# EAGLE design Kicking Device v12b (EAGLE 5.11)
OC_FARNELL: 1685056

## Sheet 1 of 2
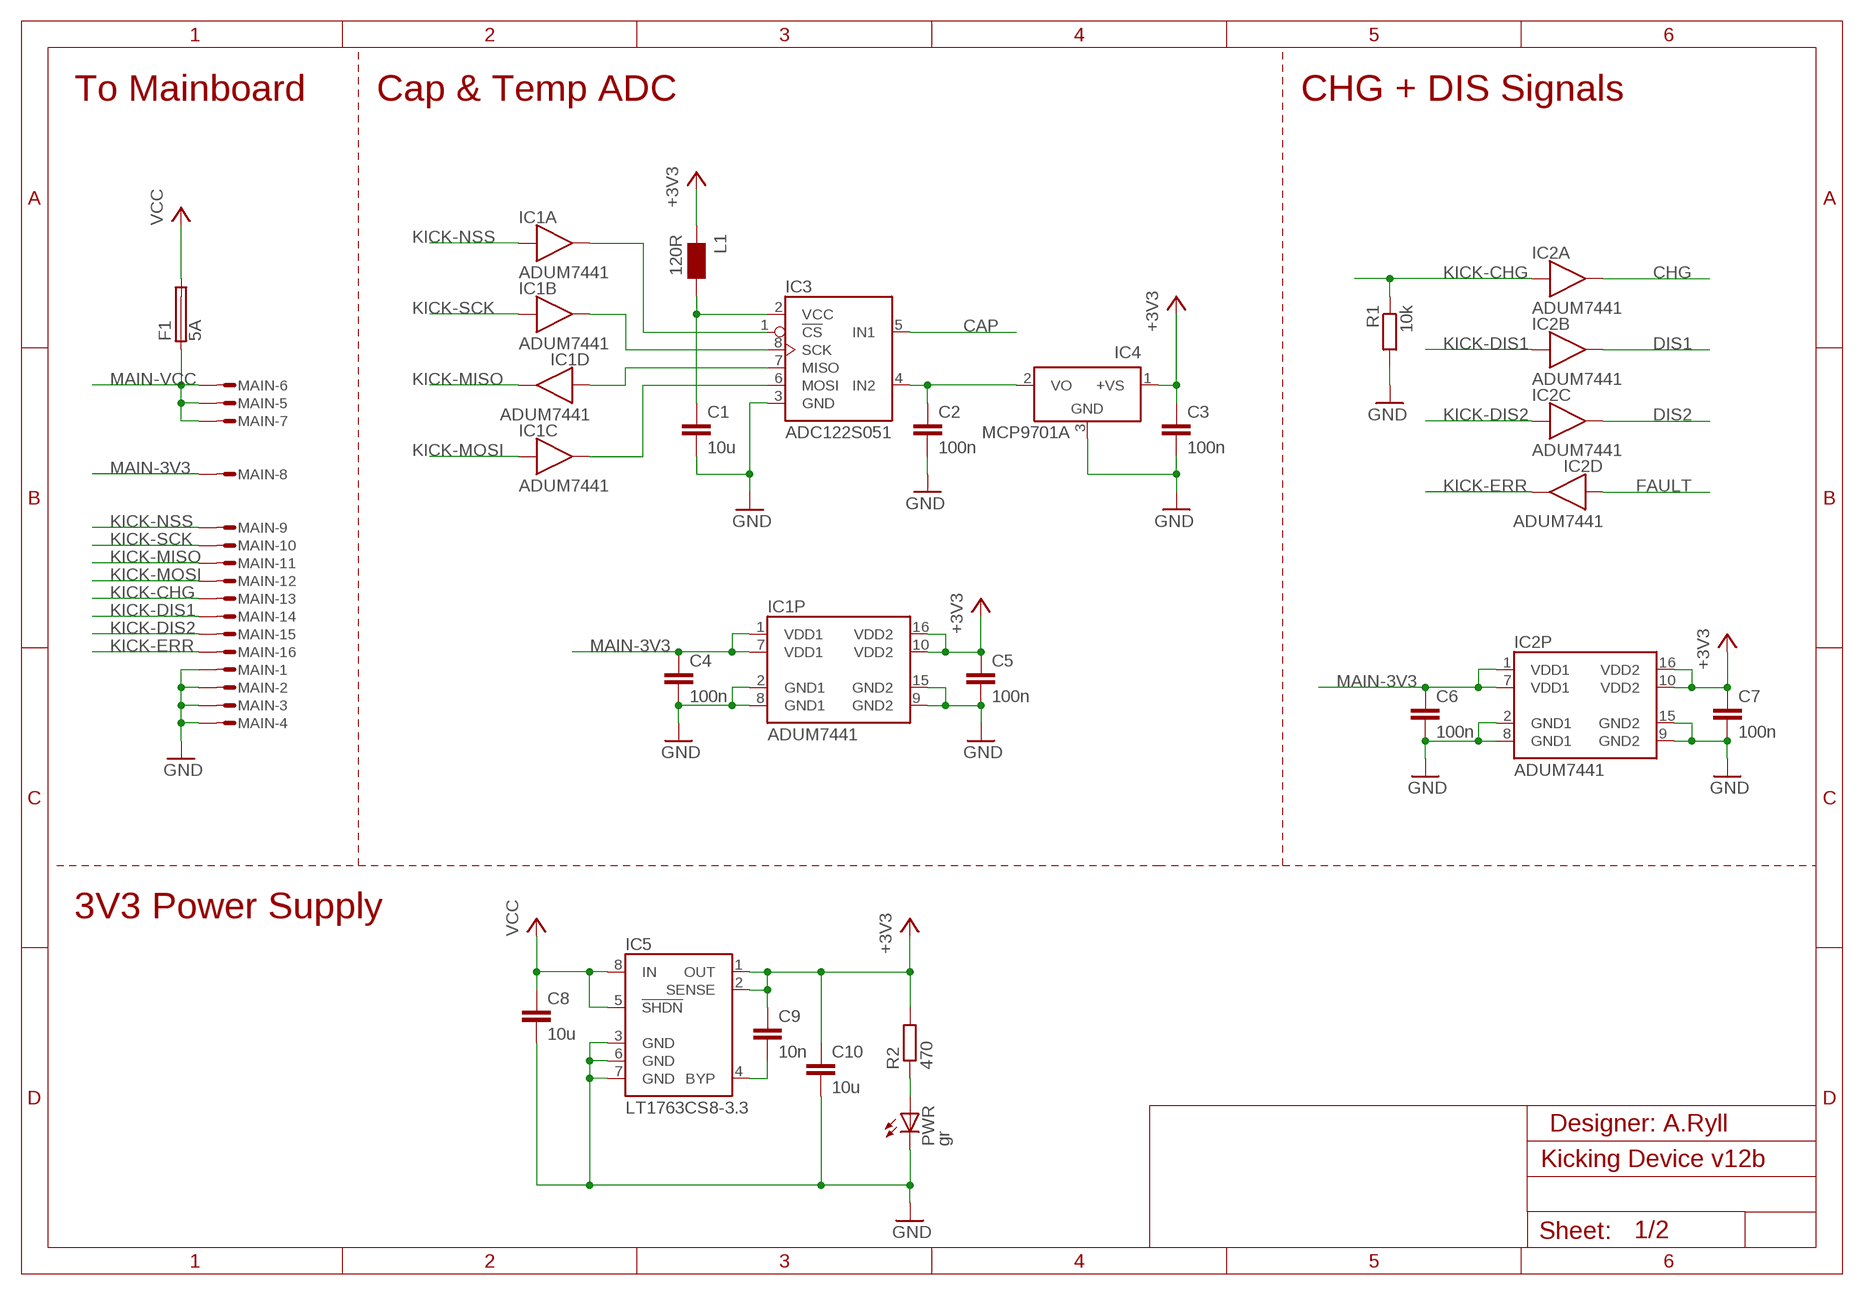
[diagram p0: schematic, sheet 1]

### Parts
C1  10u  C-EUC0603  [C0603]
C2  100n  C-EUC0603  [C0603]
C3  100n  C-EUC0603  [C0603]
C4  100n  C-EUC0603  [C0603]
C5  100n  C-EUC0603  [C0603]
C6  100n  C-EUC0603  [C0603]
C7  100n  C-EUC0603  [C0603]
C8  10u  C-EUC0805  [C0805]
C9  10n  C-EUC0603  [C0603]
C10  10u  C-EUC0603  [C0603]
F1  5A  FUSES  [1206]
IC1  ADUM7441  [QSOP16]
IC2  ADUM7441  [QSOP16]
IC3  ADC122S051  ADC__2S__1  [MSOP8]
IC4  MCP9701A  LM60S  [SOT23]
IC5  LT1763CS8-3.3  LT1763S8  [SOIC8]
L1  120R  WE-CBF_0603  [0603]
MAIN  MICROMATCH-16SMF  [MMT-F-SMD-16]
PWR  gr  LEDCHIP-LED0603  [CHIP-LED0603]
R1  10k  R-EU_R0603  [R0603]
R2  470  R-EU_R0603  [R0603]

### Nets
+3V3: C3.1 C5.1 C7.1 C9.1 C10.1 IC1.10(P:VDD2) IC1.16(P:VDD2) IC2.10(P:VDD2) IC2.16(P:VDD2) IC4.1(+VS) IC5.1(OUT) IC5.2(SENSE) L1.1 R2.2 ; also sheet 2
ADC-VCC: C1.1 IC3.2(VCC) L1.2
CAP: IC3.5(IN1) ; also sheet 2
CHG: IC2.14(A:OUT) ; also sheet 2
DIS1: IC2.13(B:OUT) ; also sheet 2
DIS2: IC2.12(C:OUT) ; also sheet 2
FAULT: IC2.11(D:IN) ; also sheet 2
GND: C1.2 C2.2 C3.2 C4.2 C5.2 C6.2 C7.2 C8.2 C10.2 IC1.2(P:GND1) IC1.8(P:GND1) IC1.9(P:GND2) IC1.15(P:GND2) IC2.2(P:GND1) IC2.8(P:GND1) IC2.9(P:GND2) IC2.15(P:GND2) IC3.3(GND) IC4.3(GND) IC5.3(GND) IC5.6(GND) IC5.7(GND) MAIN.1 MAIN.2 MAIN.3 MAIN.4 PWR.C R1.2 ; also sheet 2
KICK-CHG: IC2.3(A:IN) MAIN.13 R1.1
KICK-DIS1: IC2.4(B:IN) MAIN.14
KICK-DIS2: IC2.5(C:IN) MAIN.15
KICK-ERR: IC2.6(D:OUT) MAIN.16
KICK-MISO: IC1.6(D:OUT) MAIN.11
KICK-MOSI: IC1.5(C:IN) MAIN.12
KICK-NSS: IC1.3(A:IN) MAIN.9
KICK-SCK: IC1.4(B:IN) MAIN.10
MAIN-3V3: C4.1 C6.1 IC1.1(P:VDD1) IC1.7(P:VDD1) IC2.1(P:VDD1) IC2.7(P:VDD1) MAIN.8
MAIN-VCC: F1.1 MAIN.5 MAIN.6 MAIN.7
N$1: IC1.13(B:OUT) IC3.8(SCK)
N$3: C9.2 IC5.4(BYP)
N$7: IC1.11(D:IN) IC3.7(MISO)
N$9: PWR.A R2.1
N$15: IC1.12(C:OUT) IC3.6(MOSI)
N$16: IC1.14(A:OUT) IC3.1(!CS)
N$18: C2.1 IC3.4(IN2) IC4.2(VO)
VCC: C8.1 F1.2 IC5.5(!SHDN) IC5.8(IN) ; also sheet 2

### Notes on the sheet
- To Mainboard | Cap & Temp ADC | CHG + DIS Signals
- 3V3 Power Supply
- Designer: A.Ryll

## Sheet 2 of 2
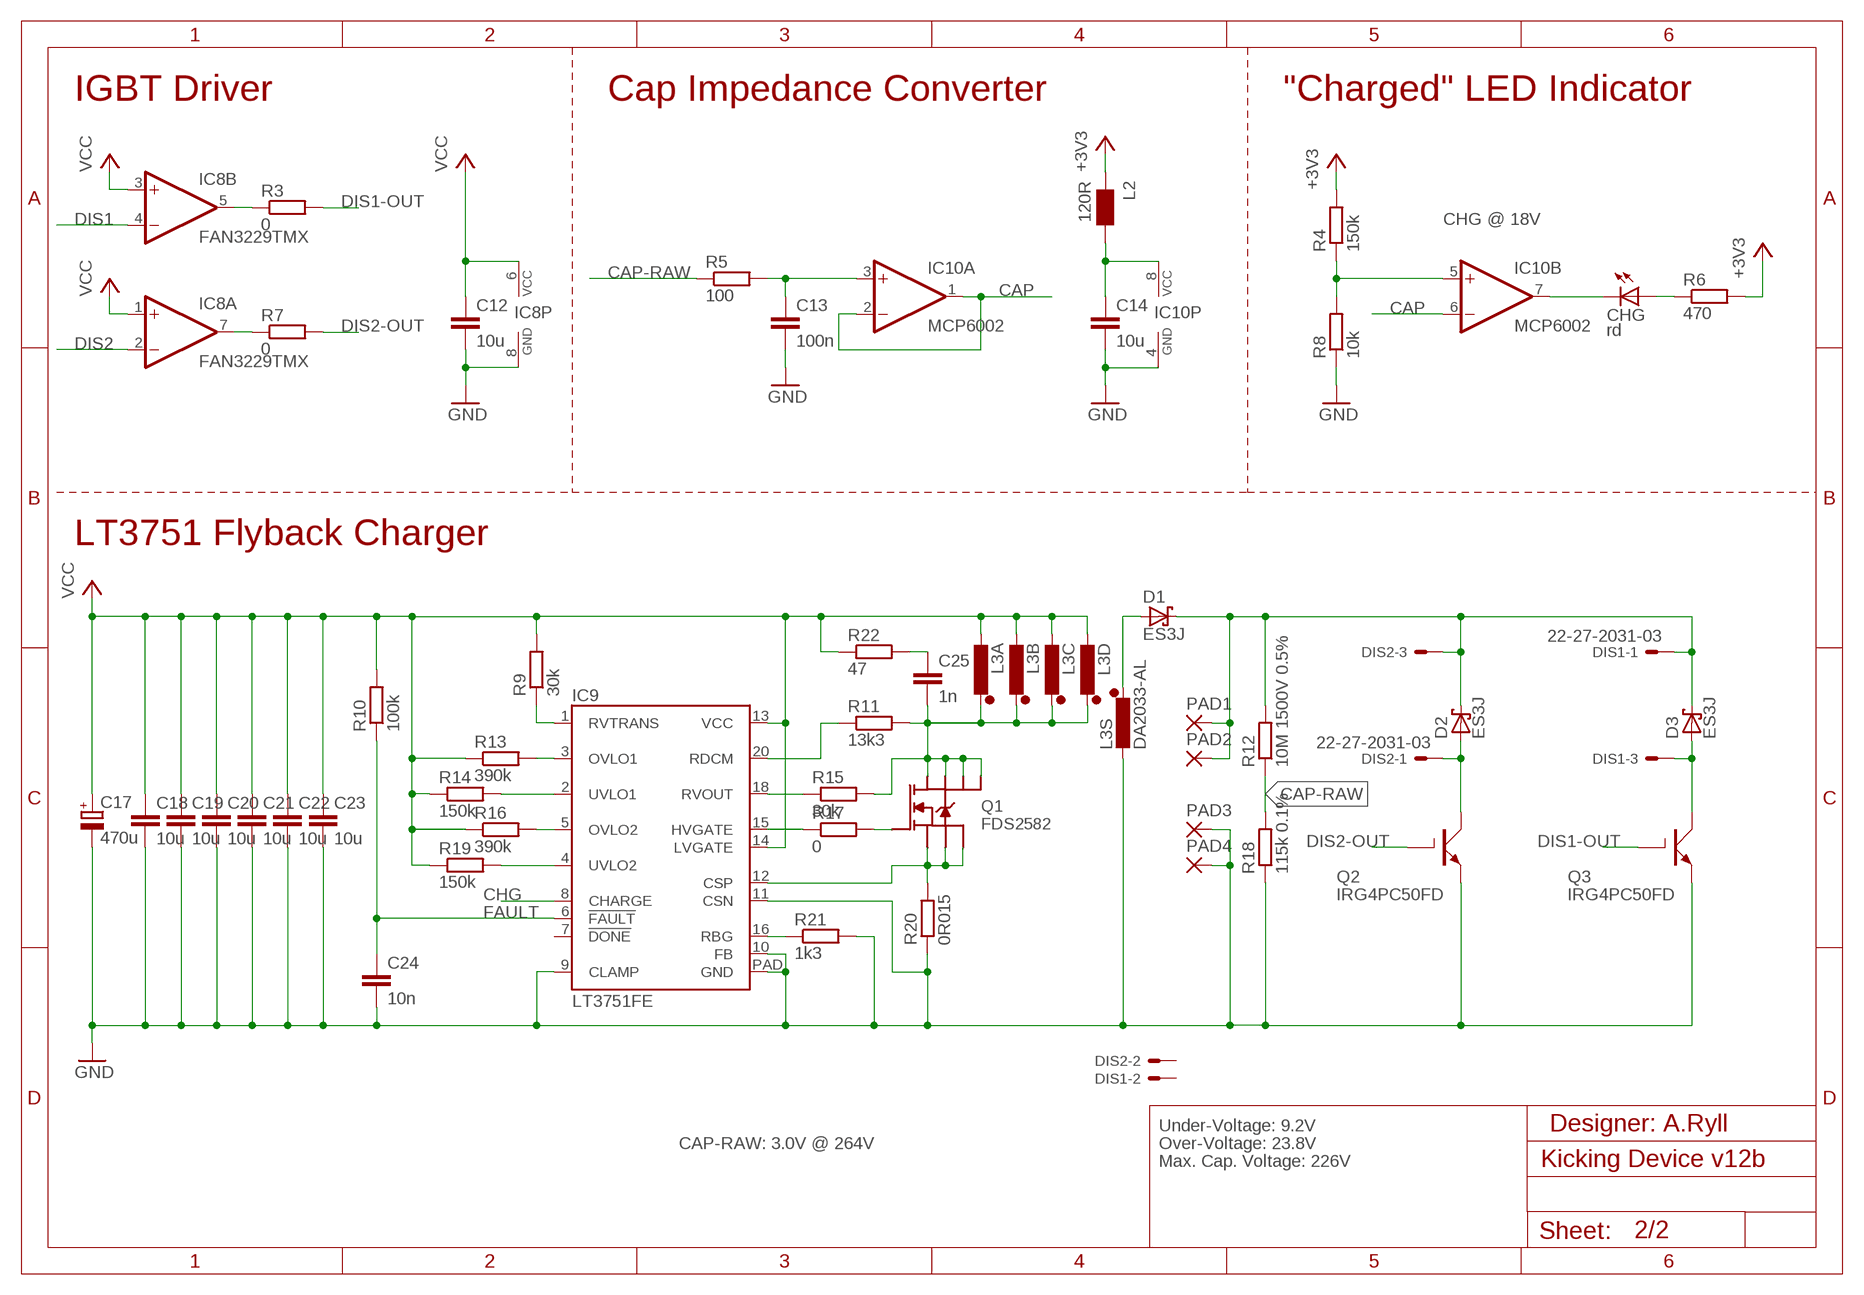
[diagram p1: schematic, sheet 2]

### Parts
C12  10u  C-EUC0805  [C0805]
C13  100n  C-EUC0603  [C0603]
C14  10u  C-EUC0603  [C0603]
C17  470u  CPOL-EUG  [PANASONIC_G]
C18  10u  C-EUC0805  [C0805]
C19  10u  C-EUC0805  [C0805]
C20  10u  C-EUC0805  [C0805]
C21  10u  C-EUC0805  [C0805]
C22  10u  C-EUC0805  [C0805]
C23  10u  C-EUC0805  [C0805]
C24  10n  C-EUC0603  [C0603]
C25  1n  C-EUC0805  [C0805]
CHG  rd  LEDCHIP-LED0603  [CHIP-LED0603]
D1  ES3J  SCHOTTKY-DIODESMC  [SMC]
D2  ES3J  SCHOTTKY-DIODESMC  [SMC]
D3  ES3J  SCHOTTKY-DIODESMC  [SMC]
DIS1  22-27-2031-03  [6410-03]
DIS2  22-27-2031-03  [6410-03]
IC8  FAN3229TMX  FAN3229_MX  [SOIC8]
IC9  LT3751FE  [TSSOP20P]
IC10  MCP6002  AD-OP2S  [SOIC8]
L2  120R  WE-CBF_0603  [0603]
L3  DA2033-AL  DA203X-AL  [DA2033-AL]
PAD1  SMD5  [SMD2,54-5,08]
PAD2  SMD5  [SMD2,54-5,08]
PAD3  SMD5  [SMD2,54-5,08]
PAD4  SMD5  [SMD2,54-5,08]
Q1  FDS2582  NMOS4D  [SOIC8]
Q2  IRG4PC50FD  IGBTTO247BV  [TO247BV]
Q3  IRG4PC50FD  IGBTTO247BV  [TO247BV]
R3  0  R-EU_R1206  [R1206]
R4  150k  R-EU_R0603  [R0603]
R5  100  R-EU_R0603  [R0603]
R6  470  R-EU_R0603  [R0603]
R7  0  R-EU_R1206  [R1206]
R8  10k  R-EU_R0603  [R0603]
R9  30k  R-EU_R0603  [R0603]
R10  100k  R-EU_R0603  [R0603]
R11  13k3  R-EU_R0603  [R0603]
R12  10M 1500V 0.5%  R-EU_R1206  [R1206]
R13  390k  R-EU_R0603  [R0603]
R14  150k  R-EU_R0603  [R0603]
R15  30k  R-EU_R0603  [R0603]
R16  390k  R-EU_R0603  [R0603]
R17  0  R-EU_R1206  [R1206]
R18  115k 0.1%  R-EU_R1206  [R1206]
R19  150k  R-EU_R0603  [R0603]
R20  0R015  R-EU_R1206  [R1206]
R21  1k3  R-EU_R0603  [R0603]
R22  47  R-EU_R0805  [R0805]

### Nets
+3V3: L2.1 R4.2 R6.2 ; also sheet 1
CAP: IC10.1(A:OUT) IC10.2(A:-IN) IC10.6(B:-IN) ; also sheet 1
CAP-RAW: R5.1 R12.1 R18.2
CAPVCC [HV]: D1.C D2.C D3.C DIS1.1 DIS2.3 PAD1.1(P) PAD2.1(P) R12.2
CHG: IC9.8(CHARGE) ; also sheet 1
CHG-LED: CHG.C IC10.7(B:OUT)
CSP: IC9.12(CSP) Q1.1(S1) Q1.2(S2) Q1.3(S3) R20.2
DIS1: IC8.4(B:-IN) ; also sheet 1
DIS1-OUT: Q3.1(G) R3.2
DIS1-SW [HV]: D2.A DIS2.1 Q2.2(C)
DIS2: IC8.2(A:-IN) ; also sheet 1
DIS2-OUT: Q2.1(G) R7.2
DIS2-SW [HV]: D3.A DIS1.3 Q3.2(C)
FAULT: C24.1 IC9.6(!FAULT) R10.1 ; also sheet 1
GND: C12.2 C13.2 C14.2 C17.- C18.2 C19.2 C20.2 C21.2 C22.2 C23.2 C24.2 IC8.8(P:GND) IC9.9(CLAMP) IC9.10(FB) IC9.11(CSN) IC9.PAD(GND) IC10.4(P:GND) L3.12 PAD3.1(P) PAD4.1(P) Q2.3(E) Q3.3(E) R8.1 R18.1 R20.1 R21.2 ; also sheet 1
LOUT: D1.A L3.1
N$2: IC10.5(B:+IN) R4.1 R8.2
N$4: Q1.4(G) R17.2
N$5: IC8.5(B:OUT) R3.1
N$6: CHG.A R6.1
N$8: IC9.16(RBG) R21.1
N$10: IC9.3(OVLO1) R13.2
N$11: C25.1 R22.2
N$12: C13.1 IC10.3(A:+IN) R5.2
N$14: IC9.15(HVGATE) R17.1
N$17: IC8.7(A:OUT) R7.1
N$21: IC9.1(RVTRANS) R9.1
N$22: IC9.2(UVLO1) R14.2
N$23: IC9.5(OVLO2) R16.2
N$25: IC9.18(RVOUT) R15.1
N$26: IC9.4(UVLO2) R19.2
N$27: IC9.20(RDCM) R11.1
OP-VCC: C14.1 IC10.8(P:VCC) L2.2
VCC: C12.1 C17.+ C18.1 C19.1 C20.1 C21.1 C22.1 C23.1 IC8.1(A:+IN) IC8.3(B:+IN) IC8.6(P:VCC) IC9.13(VCC) IC9.14(LVGATE) L3.3 L3.4 L3.5 L3.6 R9.2 R10.2 R13.1 R14.1 R16.1 R19.1 R22.1 ; also sheet 1
VDRAIN: C25.2 L3.7 L3.8 L3.9 L3.10 Q1.5(D1) Q1.6(D2) Q1.7(D3) Q1.8(D4) R11.2 R15.2
Unconnected: DIS1.2 DIS2.2 IC9.7(!DONE)

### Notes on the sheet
- IGBT Driver | Cap Impedance Converter | "Charged" LED Indicator
- CHG @ 18V
- LT3751 Flyback Charger
- Under-Voltage: 9.2V | Designer: A.Ryll
- CAP-RAW: 3.0V @ 264V | Over-Voltage: 23.8V
- Max. Cap. Voltage: 226V

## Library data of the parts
C1-C10 C12-C14 C18-C25 = rcl:C-EU: CAPACITOR, European symbol
C17 = rcl:CPOL-EU: POLARIZED CAPACITOR, European symbol
CHG PWR = led:LED: LED
D1-D3 = diode:SCHOTTKY-DIODE: Schottky Diode
DIS1 DIS2 = con-molex:22-?-03: CONNECTOR wire to board 2.54 mm (.1 inch) pitch header
F1 = Marvin:FUSE: 1 SCHURTER 0031.3558
IC1 IC2 = Marvin:ADUM744
IC3 = Marvin:ADC__2S__1
IC4 = Marvin:LM60: LM60 Temperature Sensor -40°C to 125°C
IC5 = Marvin:LT1763: Low-Noise LDO 500mA, Low Noise, LDO Micropower Regulators
IC8 = Marvin:FAN322
IC9 = Marvin:LT3751
IC10 = Marvin:AD-OP2
L1 L2 = wuerth-elektronik:WE-CBF: SMD EMI Suppression Ferrite Beads
L3 = Marvin:DA203X-AL
MAIN = con-amp-micromatch:MICROMATCH-16: MicroMaTch 16 8-215464-6 / 1-215464-6 Drawing Number C-215464 DDEController.pdf
PAD1-PAD4 = wirepad:SMD5: SMD PAD
Q1 = Marvin:NMOS4D
Q2 Q3 = Marvin:IGBT
R1-R22 = rcl:R-EU_: RESISTOR, European symbol

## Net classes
0 default: width 0.152 mm, clearance 0.152 mm
1 HV: width 0.203 mm, drill 0.305 mm, clearance 1.016 mm to class 0, clearance 1.016 mm

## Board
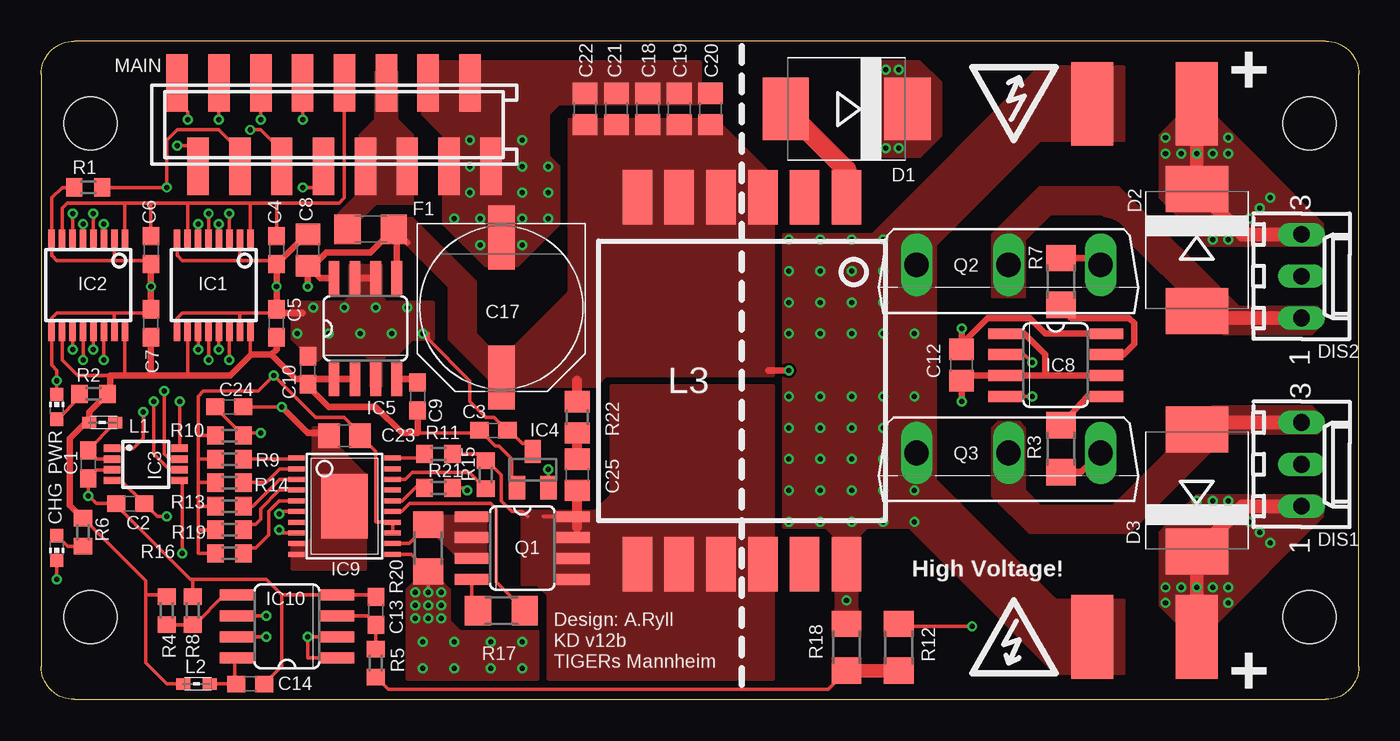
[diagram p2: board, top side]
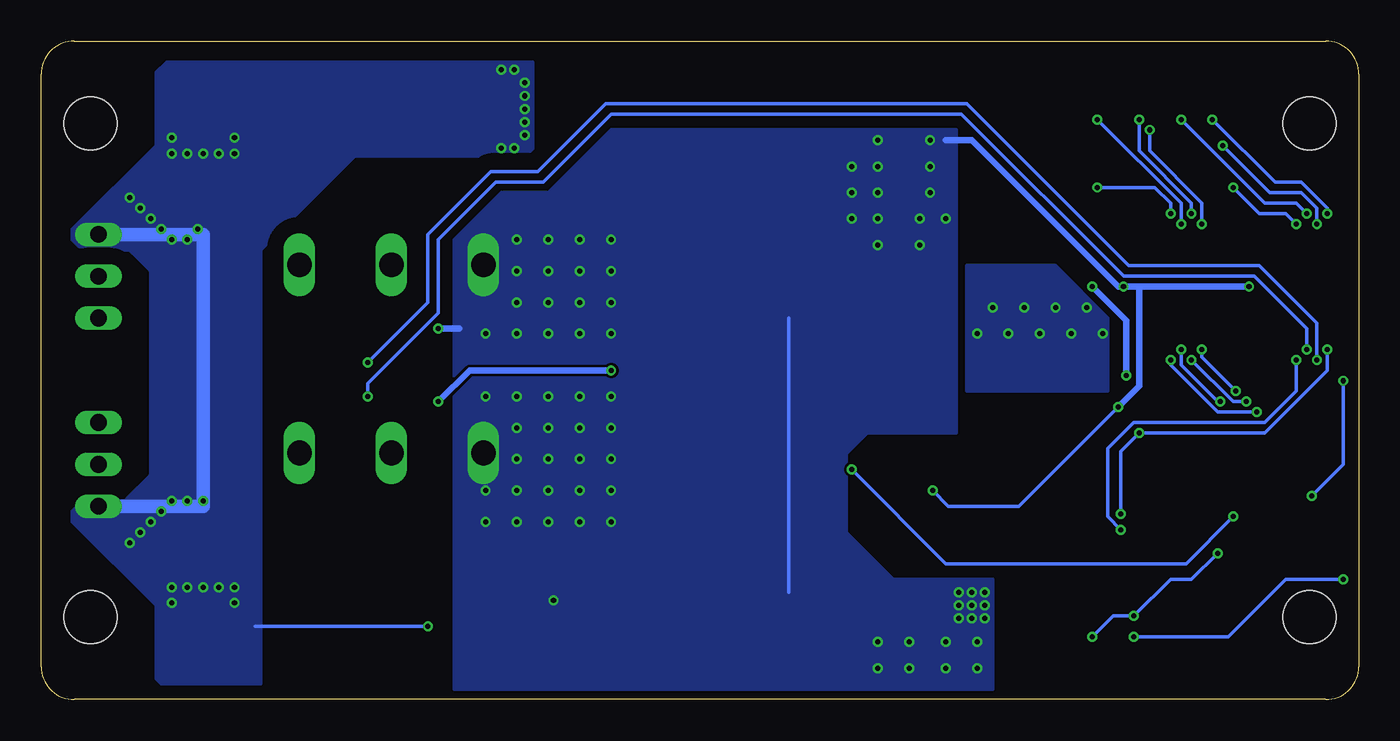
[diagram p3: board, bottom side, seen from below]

Size 80 x 40 mm. Coordinates in mm from the lower left corner, seen from the top.
Outline: 2,0 78,0 arc90 80,2 80,38 arc90 78,40 2,40 arc90 0,38 0,2 arc90 2,0
Copper layers (1*16): Top 0.035mm / dielectric 1.5mm / Bottom 0.035mm
Design rules "PCB-POOL Standard *": minimum track width 0.15mm, minimum drill 0.3mm, track to track 0.15mm, track to pad 0.15mm, pad to pad 0.15mm, via to via 0.15mm, smd to smd 0.15mm, copper to edge 0.3mm, drill to drill 0.2mm, minimum pad ring 0.2mm, minimum via ring 0.15mm, stop-mask expansion 0.075mm, vias tented up to drill 0mil, thermal gap 0.2mm
Holes 3.2 mm at 77,5 77,35 3,35 3,5
tKeepout: area 74,32 to 80,38; area 74,2 to 80,8; area 0,32 to 6,38; area 0,2 to 6,8; area 50.8,28.9 to 66.7,49.8
bKeepout: area 21.6,12.1 to 29.8,15.2

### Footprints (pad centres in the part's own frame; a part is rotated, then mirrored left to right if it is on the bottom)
C0603 = smd 1.1 x 1: 1 -0.85,0; 2 0.85,0
C0805 = smd 1.3 x 1.5: 1 -0.95,0; 2 0.95,0
PANASONIC_G = smd 3.9 x 1.6: + 4.25,0; - -4.25,0
CHIP-LED0603 = smd 0.8 x 0.8: A 0,-0.75; C 0,0.75
SMC = smd 2.8 x 3.8: A 3.7,0; C -3.7,0
6410-03 = drill 1.016 long: 1 2.54,0; 2 0,0; 3 -2.54,0
1206 = smd 1.6 x 1.8: 1 -1.4,0; 2 1.4,0
QSOP16 = smd 0.4 x 1.2: 1 -2.223,-2.857; 2 -1.587,-2.857; 3 -0.953,-2.858; 4 -0.318,-2.858; 5 0.318,-2.857; 6 0.953,-2.857; 7 1.587,-2.857; 8 2.223,-2.857; 9 2.223,2.699; 10 1.587,2.699; 11 0.953,2.699; 12 0.318,2.699; 13 -0.318,2.699; 14 -0.953,2.699; 15 -1.587,2.699; 16 -2.223,2.699
MSOP8 = smd 0.45 x 1: 1 -0.975,-2.05; 2 -0.325,-2.05; 3 0.325,-2.05; 4 0.975,-2.05; 5 0.975,2.05; 6 0.325,2.05; 7 -0.325,2.05; 8 -0.975,2.05
SOT23 = smd 1 x 1.4: 1 -0.95,-1.1; 2 0.95,-1.1; 3 0,1.1
SOIC8 = smd 0.66 x 2.032: 1 -1.905,-3.073; 2 -0.635,-3.073; 3 0.635,-3.073; 4 1.905,-3.073; 5 1.905,3.073; 6 0.635,3.073; 7 -0.635,3.073; 8 -1.905,3.073
TSSOP20P = smd 0.305 x 0.991: 1 -2.925,-2.918; 2 -2.275,-2.918; 3 -1.625,-2.918; 4 -0.975,-2.918; 5 -0.325,-2.918; 6 0.325,-2.918; 7 0.975,-2.918; 8 1.625,-2.918; 9 2.275,-2.918; 10 2.925,-2.918; 11 2.925,2.918; 12 2.275,2.918; 13 1.625,2.918; 14 0.975,2.918; 15 0.325,2.918; 16 -0.325,2.918; 17 -0.975,2.918; 18 -1.625,2.918; 19 -2.275,2.918; 20 -2.925,2.918 | smd 3.9 x 2.8: PAD 0,0
0603 = smd 0.85 x 0.7: 1 -0.9,0; 2 0.7,0
DA2033-AL = smd 3.3 x 1.8: 1 -11.15,6.35; 2 -11.15,3.81; 3 -11.15,1.27; 4 -11.15,-1.27; 5 -11.15,-3.81; 6 -11.15,-6.35; 7 11.15,-6.35; 8 11.15,-3.81; 9 11.15,-1.27; 10 11.15,1.27; 11 11.15,3.81; 12 11.15,6.35
MMT-F-SMD-16 = smd 1.3 x 3.5: 1 9.525,-2.54; 2 8.255,2.54; 3 6.985,-2.54; 4 5.715,2.54; 5 4.445,-2.54; 6 3.175,2.54; 7 1.905,-2.54; 8 0.635,2.54; 9 -0.635,-2.54; 10 -1.905,2.54; 11 -3.175,-2.54; 12 -4.445,2.54; 13 -5.715,-2.54; 14 -6.985,2.54; 15 -8.255,-2.54; 16 -9.525,2.54
SMD2,54-5,08 = smd 2.54 x 5.08: 1 0,0
TO247BV = drill 1.499 long: 1 -5.588,-2.921; 2 0,-2.921; 3 5.588,-2.921
R0603 = smd 1 x 1.1: 1 -0.85,0; 2 0.85,0
R1206 = smd 1.6 x 1.803: 1 -1.422,0; 2 1.422,0
R0805 = smd 1.3 x 1.5: 1 -0.95,0; 2 0.95,0

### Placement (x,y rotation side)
C1  2.86,14.29 270 top
C2  5.4,11.91 180 top
C3  27.46,16.35 0 top
C4  14.29,27.3 270 top
C5  14.29,22.86 90 top
C6  6.67,27.3 270 top
C7  6.67,22.86 90 top
C8  16.19,27.3 90 top
C9  22.86,18.41 90 top
C10  16.19,20 90 top
C12  55.88,20.32 90 top
C13  20.32,5.4 90 top
C14  12.7,0.95 0 top
C17  27.94,23.81 270 top
C18  36.83,35.88 90 top
C19  38.73,35.88 90 top
C20  40.64,35.88 90 top
C21  34.92,35.88 90 top
C22  33.02,35.88 90 top
C23  18.42,16.03 180 top
C24  11.43,17.78 0 top
C25  32.54,13.65 270 top
CHG  0.95,9.21 180 top
D1  48.9,35.88 180 top
D2  70.17,27.3 270 top
D3  70.17,12.7 90 top
DIS1  76.52,14.29 270 top
DIS2  76.52,25.72 270 top
F1  20,28.57 0 top
IC1  10.48,25.08 180 top
IC2  2.86,25.08 180 top
IC3  6.35,14.29 270 top
IC4  29.85,13.97 0 top
IC5  19.68,22.54 0 top
IC8  61.59,20.32 270 top
IC9  18.41,11.75 270 top
IC10  14.92,4.45 90 top
L1  3.81,16.83 0 top
L2  9.53,0.95 0 top
L3  42.55,19.37 270 top
MAIN  17.78,34.92 0 top
PAD1  70.17,3.81 0 top
PAD2  70.17,36.2 0 top
PAD3  63.82,3.81 0 top
PAD4  63.82,36.2 0 top
PWR  0.95,17.78 0 top
Q1  29.21,9.21 270 top
Q2  58.74,23.5 180 top
Q3  58.74,12.06 180 top
R1  2.86,31.11 180 top
R2  3.17,18.57 0 top
R3  61.91,15.24 270 top
R4  7.62,5.4 90 top
R5  20.32,2.22 90 top
R6  2.54,10.16 90 top
R7  61.91,25.4 90 top
R8  9.21,5.4 270 top
R9  11.43,14.61 180 top
R10  11.43,16.03 180 top
R11  24.13,14.92 0 top
R12  52.07,3.17 90 top
R13  11.43,11.75 0 top
R14  11.43,13.18 0 top
R15  26.99,13.65 90 top
R16  11.43,8.89 0 top
R17  27.94,5.4 180 top
R18  48.9,3.17 270 top
R19  11.43,10.32 0 top
R20  23.5,9.21 90 top
R21  24.13,12.86 0 top
R22  32.54,17.14 270 top

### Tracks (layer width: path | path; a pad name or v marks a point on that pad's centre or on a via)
+3V3
  Top 0.203: 4.18,19.68 2.22,19.68 1.27,20.64 IC2.10 | 5.08,19.68 5.13,19.74 5.08,19.79 IC2.16 | 8.89,19.68 IC1.10 | IC1.16 12.7,21.01 12.75,20.95 | IC4.1 28.57,13.35 28.57,14.61 27.78,15.4 27.57,15.4 C3.1 26.45,16.19 22.86,16.19 | R6.2 6.35,7.2 6.35,6.35 | 6.35,6.35 6.35,2.22 7.62,0.95 L2.1 | R4.2 7.52,6.35 6.35,6.35
  Top 0.406: C5.1 14.29,21.27 13.97,20.95 | 13.97,20.95 12.75,20.95 11.48,19.68 8.89,19.68 6.67,19.68 | 6.67,19.68 C7.1 | 6.67,19.68 5.08,19.68 4.18,19.68 4.18,18.73 R2.2 2.91,17.46 L1.1 2.7,16.83 1.75,15.88 1.75,11.8 R6.2 | IC5.2 IC5.1 16.51,19.47 | 16.51,19.47 C10.1 16.19,19.05 17.46,17.78 20.32,17.78 21.91,16.19 22.86,16.19 C9.1 | 16.51,19.47 15.46,19.47 13.97,20.95
ADC-VCC
  Top 0.203: C1.1 2.75,15.24 | IC3.2 3.38,14.61 C1.1 | L1.2 2.86,15.18 C1.1
CAP  (via drill 0.3, 0.3 pad 0.3)
  Top 0.203: v8.57,8.89 8.57,13.14 IC3.5 | IC10.1 16.19,2.54 v16.19,3.81 IC10.2 | IC10.6 v13.65,5.08
  Bottom 0.203: v8.57,8.89 10.16,7.3 11.43,7.3 v13.65,5.08 14.92,5.08 v16.19,3.81
CAP-RAW
  Top 0.203: R18.2 47.78,0.64 21.06,0.64 R5.1
  Top 0.813: R18.2 R12.1
CAPVCC  (via drill 0.3)
  Top 0.203: R12.2 52.22,4.45 v56.52,4.45
  Top 0.813: PAD1.1 D3.C 72.92,11.75 DIS1.1 | DIS2.3 72.92,28.26 D2.C PAD2.1
  Bottom 0.203: v56.52,4.45 66.99,4.45
  Bottom 0.813: DIS1.1 70.17,11.75 70.17,28.26 DIS2.3
  other vias: 68.26,6.83 70.17,6.83 71.12,6.83 69.22,6.83 72.07,6.83 72.07,5.87 68.26,5.87 70.17,33.18 71.12,33.18 72.07,33.18 72.07,34.13 69.22,33.18 68.26,33.18 68.26,34.13 70.48,28.58 71.12,27.94 72.07,27.94 72.71,28.58 73.34,29.21 73.98,29.85 74.61,30.48 70.17,12.07 71.12,12.07 72.07,12.07 72.71,11.43 73.34,10.8 73.98,10.16 74.61,9.53 50.64,35.88 52.07,38.26 51.28,38.26 50.64,37.47 50.64,36.67 50.64,35.08 50.64,34.29 51.28,33.5 52.07,33.5
  pour Top (no thermals): 69.22,4.45 67.94,5.71 67.94,10.16 70.17,12.38 77.47,12.38 77.79,12.06 77.79,11.11 71.12,4.45
  pour Top (no thermals): 69.22,35.56 67.94,34.29 67.94,30.48 70.8,27.62 77.47,27.62 77.79,27.94 77.79,28.89 71.12,35.56
  pour Bottom (no thermals): 50.16,33.02 60.96,33.02 66.67,27.3 66.67,0.95 72.71,0.95 73.03,1.27 73.03,5.71 78.11,10.79 78.11,11.43 77.47,12.06 74.93,12.06 73.34,13.65 73.34,26.04 74.61,27.3 77.47,27.3 78.11,27.94 78.11,28.57 73.03,33.66 73.03,38.1 72.39,38.73 50.16,38.73
  pour Top (no thermals): 54.61,34.29 53.34,33.02 51.12,33.02 50.16,33.97 50.16,38.1 50.8,38.73 53.34,38.73 54.61,37.47
CHG  (via drill 0.3)
  Top 0.203: v3.81,20.64 IC2.14 | IC9.8 14.64,10.12 v14.45,10.32
  Bottom 0.203: v14.45,10.32 | v14.45,10.32 15.24,11.11 15.24,15.24 13.65,16.83 5.71,16.83 3.81,18.73 v3.81,20.64
CHG-LED  (via drill 0.3, 0.3 pad 0.3)
  Top 0.203: v0.95,7.3 CHG.C | v13.65,3.81 IC10.7
  Bottom 0.203: v13.65,3.81 7.94,3.81 4.45,7.3 v0.95,7.3
CSP
  Top 0.203: IC9.12 22.34,9.47 R20.2
  pour Top (no thermals): 26.99,8.57 26.99,11.11 22.86,11.11 22.86,10.16 23.81,10.16 25.4,8.57
DIS1  (via drill 0.3)
  Top 0.203: IC2.13 v3.17,21.27 | v60.17,18.41 IC8.4
  Bottom 0.203: v3.17,21.27 3.17,22.54 6.35,25.72 14.29,25.72 24.13,35.56 45.4,35.56 49.53,31.43 52.39,31.43 55.88,27.94 55.88,23.5 60.17,19.21 v60.17,18.41
DIS1-OUT
  Top 0.406: R3.2 63.16,13.82 Q3.1
DIS1-SW
  Top 0.813: DIS2.1 70.59,23.18 D2.A
  pour Top (no thermals): 58.1,24.13 57.78,24.45 57.78,28.26 60.64,31.11 65.4,31.11 72.71,23.81 77.47,23.81 77.79,23.5 77.79,22.86 77.15,22.23 71.75,22.23 64.45,29.53 61.28,29.53 59.69,27.94 59.69,24.45 59.37,24.13
DIS2  (via drill 0.3)
  Top 0.203: IC2.12 v2.54,20.64 | IC8.2 59.69,20.95 v60.17,20.48
  Bottom 0.203: v2.54,20.64 2.54,22.86 6.03,26.35 13.97,26.35 23.81,36.2 45.72,36.2 49.85,32.07 52.7,32.07 56.52,28.26 56.52,24.13 v60.17,20.48
DIS2-OUT
  Top 0.406: R7.2 63.92,26.82 Q2.1
DIS2-SW
  Top 0.813: DIS1.3 70.59,16.83 D3.A
  pour Top (no thermals): 58.1,16.83 57.78,16.51 57.78,12.38 60.01,10.16 66.04,10.16 72.07,16.19 77.47,16.19 77.79,16.51 77.79,17.14 77.15,17.78 71.12,17.78 65.09,11.75 60.64,11.75 59.69,12.7 59.69,16.51 59.37,16.83
FAULT  (via drill 0.3)
  Top 0.203: v1.91,21.27 IC2.11 | IC9.6 14.6,11.42 v14.45,11.27 | 12.38,15.93 R10.1 10.58,17.73 C24.1 | 12.38,15.93 12.44,15.88 | 12.38,15.93 12.38,16.19 v13.34,16.19
  Bottom 0.203: v1.91,21.27 1.91,20 5.71,16.19 v13.34,16.19 14.45,15.08 v14.45,11.27 14.61,11.43
GND  (via drill 0.3)
  Top 0.203: C1.2 2.75,13.34 | IC3.3 3.38,13.96 C1.2 | C7.2 6.45,23.5 4.45,23.5 | 4.45,23.5 0.95,23.5 0.64,23.18 IC2.9 0.64,20.32 0.95,20 v0.95,19.37 PWR.C | 4.45,26.67 6.45,26.67 C6.2 | 4.45,26.67 0.95,26.67 0.64,26.99 IC2.8 0.64,30.48 1.27,31.11 R1.2 | 12.06,26.67 14.07,26.67 C4.2 | 12.06,26.67 8.57,26.67 8.26,26.99 IC1.8 | 12.06,23.5 14.07,23.5 C5.2 | 12.06,23.5 8.57,23.5 8.26,23.18 IC1.9 | 12.06,22.2 IC1.15 12.06,23.5 | 12.06,27.97 IC1.2 12.06,26.67 | 4.45,27.97 IC2.2 4.45,26.67 | 4.45,23.5 IC2.15 | v23.5,6.51 R20.1 22.46,8.82 IC9.11 | 23.5,22.23 23.5,21.91 26.04,19.37 26.04,18.1 26.99,17.14 27.52,17.14 C3.2 28.42,16.35 29.21,15.56 29.69,15.56 IC4.3 | v14.61,17.78 C24.2 | C1.2 v2.86,12.38 3.33,11.91 C2.2 4.55,11.8 9.05,7.3 9.21,7.3 | R21.2 25.72,12.86 v25.88,12.7 | C14.2 14.61,2.01 14.61,6.35 | 14.61,6.35 13.65,7.3 9.21,7.3 | 9.21,7.3 R8.1 | 14.61,6.35 IC10.4 20.22,6.35 C13.2
  Top 0.406: C7.2 v6.67,25.08 C6.2 | C5.2 v14.29,25.08 C4.2 16.09,28.25 C8.2 | IC8.8 60.96,22.23 60.01,23.18 57.47,23.18 55.88,21.59 | IC5.7 IC5.6 | 14.07,23.5 15.88,23.5 | 55.88,21.59 C12.2 | v55.88,22.54 55.88,21.59 | v14.61,17.78 16.19,16.19 17.31,16.19 C23.2
  Top 0.813: PAD4.1 64.45,35.88
  Bottom 0.203: 34.61,6.51 34.61,23.18 | v14.61,17.78 20.64,11.75 24.92,11.75 v25.88,12.7 | v0.95,19.37 0.95,14.29 v2.86,12.38
  Bottom 0.406: v6.67,25.08 13.34,25.08 | 13.34,25.08 v14.29,25.08 14.61,25.08 23.5,33.97 25.08,33.97 | 54.61,22.54 v55.88,22.54 | v14.61,17.78 13.34,19.05 13.34,25.08
  other vias: 22.7,6.51 24.29,6.51 22.7,5.72 23.5,5.72 24.29,5.72 29.21,30.8 22.7,4.92 23.5,4.92 24.29,4.92 23.18,3.49 23.18,1.91 25.08,1.91 25.08,3.49 27.3,3.49 27.3,1.91 29.21,1.91 29.21,3.49 29.21,27.62 26.67,27.62 25.08,29.21 26.03,33.97 30.8,29.21 26.67,29.21 29.21,29.21 30.8,30.8 30.8,32.38 29.21,32.38 29.21,33.97 26.03,32.38 26.03,30.8 45.4,27.94 45.4,26.04 45.4,24.13 45.4,22.23 45.4,10.79 45.4,12.7 45.4,14.61 45.4,16.51 45.4,18.41 47.31,18.41 47.31,16.51 49.21,18.41 49.21,16.51 51.12,16.51 51.12,18.41 47.31,14.61 49.21,14.61 47.31,12.7 47.31,10.79 49.21,12.7 49.21,10.79 51.12,14.61 51.12,12.7 51.12,10.79 47.31,22.23 49.21,22.23 51.12,22.23 47.31,24.13 47.31,26.04 47.31,27.94 49.21,24.13 49.21,26.04 49.21,27.94 51.12,24.13 51.12,26.04 51.12,27.94 53.02,18.41 53.02,22.23 53.02,12.7 53.02,10.79 48.9,6.03 16.51,23.81 18.41,23.81 20.32,23.81 22.23,23.81 23.18,22.23 21.27,22.23 19.37,22.23 17.46,22.23 15.56,22.23
  pour Top (no thermals): 24.45,28.89 24.45,34.29 23.18,35.56 23.18,38.73 40.01,38.73 40.01,36.2 31.43,36.2 30.8,35.56 30.8,33.02 31.43,32.38 31.43,28.89 28.89,26.35 26.99,26.35
  pour Top (no thermals): 50.48,28.26 60.64,38.42 65.72,38.42 65.72,33.97 60.64,33.97 54.29,27.62 54.29,13.34 61.59,6.03 65.72,6.03 65.72,1.59 61.59,1.59 52.7,10.48 50.16,10.48 49.53,9.84 49.53,4.13 48.26,4.13 48.26,9.84 47.62,10.48 45.09,10.48 45.09,28.26
  pour Top (no thermals): 20,19.05 20,20.64 19.68,20.95 17.14,20.95 16.83,20.64 15.88,20.64 15.88,21.27 15.24,21.91 15.24,24.13 18.41,24.13 18.73,24.45 18.73,26.35 20.64,26.35 20.64,24.45 20.95,24.13 23.81,24.13 23.81,21.91 22.54,21.91 21.59,20.95 20.95,20.95 20.64,20.64 20.64,19.05
  pour Top (no thermals): 22.86,8.26 22.86,7.3 22.23,6.67 22.23,1.27 30.16,1.27 30.16,4.13 25.4,4.13 24.77,4.76 24.77,6.67 24.13,7.3 24.13,8.26
  pour Top (no thermals): 16.51,14.92 16.51,9.84 16.19,9.53 15.24,9.53 15.24,7.94 19.68,7.94 19.68,13.65 17.94,15.4 17.94,16.51 16.51,16.51
  pour Bottom (no thermals): 31.11,10.16 31.11,14.92 29.84,16.19 24.45,16.19 24.45,34.61 45.4,34.61 49.21,30.8 52.07,30.8 54.93,27.94 54.93,0.64 22.23,0.64 22.23,7.3 28.26,7.3
  pour Bottom: 15.24,23.18 15.24,18.73 23.81,18.73 23.81,26.35 18.41,26.35
KICK-CHG  (via drill 0.3)
  Top 0.203: IC2.3 3.81,28.03 v3.81,28.89 | MAIN.13 12.06,33.34 10.79,34.61 8.26,34.61 7.62,33.97 v7.62,31.11 R1.1
  Bottom 0.203: v3.81,28.89 4.45,29.53 6.03,29.53 v7.62,31.11
KICK-DIS1  (via drill 0.3)
  Top 0.203: v10.79,35.24 MAIN.14 | IC2.4 3.17,28.02 v3.17,29.53
  Bottom 0.203: v3.17,29.53 3.81,30.16 5.71,30.16 v10.79,35.24
KICK-DIS2  (via drill 0.3)
  Top 0.203: v8.26,33.66 9.53,33.66 MAIN.15 | IC2.5 2.54,28.02 v2.54,28.89
  Bottom 0.203: v2.54,28.89 2.54,29.84 3.49,30.8 5.4,30.8 v8.26,33.66
KICK-ERR  (via drill 0.3)
  Top 0.203: v8.89,35.24 8.89,35.72 8.26,36.35 MAIN.16 | IC2.6 1.91,28.03 v1.91,29.53
  Bottom 0.203: v8.89,35.24 5.08,31.43 3.49,31.43 1.91,29.84 v1.91,29.53
KICK-MISO  (via drill 0.3)
  Top 0.203: MAIN.11 14.61,33.34 13.34,34.61 v12.7,34.61 | IC1.6 9.53,28.03 v9.53,28.89
  Bottom 0.203: v12.7,34.61 12.7,33.34 9.53,30.16 v9.53,28.89
KICK-MOSI  (via drill 0.3)
  Top 0.203: v13.34,35.24 MAIN.12 | IC1.5 10.16,28.02 v10.16,29.53
  Bottom 0.203: v13.34,35.24 13.34,33.34 10.16,30.16 v10.16,29.53 10.16,29.84
KICK-NSS  (via drill 0.3)
  Top 0.203: MAIN.9 17.14,31.11 v15.88,31.11 | IC1.3 11.43,28.03 v11.43,29.53
  Bottom 0.203: v11.43,29.53 11.43,30.16 12.38,31.11 v15.88,31.11
KICK-SCK  (via drill 0.3)
  Top 0.203: v15.88,35.24 MAIN.10 | IC1.4 10.79,28.02 v10.79,28.89
  Bottom 0.203: 10.79,29.21 v10.79,28.89 10.79,30.16 v15.88,35.24
LOUT
  Top 1.219: L3.1 48.9,32.18 D1.A
MAIN-3V3
  Top 0.203: 14.29,30.16 C4.1 | 6.67,30.16 C6.1 | 6.67,30.16 8.89,30.16 | 8.89,30.16 12.7,30.16 | 12.7,30.16 14.29,30.16 | 5.08,30.16 1.59,30.16 1.27,29.84 IC2.7 | 5.08,30.16 6.67,30.16 | 14.29,30.16 18.1,30.16 18.41,30.48 MAIN.8 | 5.08,30.16 IC2.1 | 8.89,30.16 IC1.7 | 12.7,30.16 IC1.1
MAIN-VCC
  pour Top (no thermals): 18.1,29.53 19.37,30.8 19.37,34.29 20.32,35.24 20.32,38.1 21.59,38.1 21.59,35.24 22.54,34.29 22.54,30.16 20.32,30.16 19.05,28.89 19.05,27.94 18.1,27.94
N$1  (via drill 0.3)
  Top 0.203: 8.42,15.24 IC3.8 8.41,15.28 v8.41,18.1 | v10.79,21.27 IC1.13
  Bottom 0.203: v10.79,21.27 10.79,20.32 8.57,18.1 v8.41,18.1
N$2
  Top 0.203: IC10.5 11.11,6.35 9.31,4.55 R8.2 R4.1
N$3
  Top 0.406: IC5.4 22.75,19.47 C9.2
N$4
  Top 0.203: R17.2 26.14,5.78 Q1.4
N$5
  Top 0.406: IC8.5 63.51,18.41 R3.1
N$6
  Top 0.203: 0.95,9.95 CHG.A 1.6,9.31 R6.1
N$7  (via drill 0.3)
  Top 0.203: IC3.7 7.77,14.61 7.46,14.92 v7.46,18.73 | v9.53,21.27 IC1.11
  Bottom 0.203: v7.46,18.73 9.53,20.8 v9.53,21.27
N$8
  Top 0.203: IC9.16 21.91,12.07 22.86,13.02 R21.1
N$9
  Top 0.203: PWR.A 1,17.03 2.33,18.36 R2.1
N$10
  Top 0.203: IC9.3 14.48,13.37 12.86,11.75 R13.2
N$11
  Top 0.61: C25.1 R22.2
N$12
  Top 0.203: IC10.3 19.79,5.08 C13.1 R5.2
N$14
  Top 0.203: IC9.15 21.9,11.42 22.38,11.91 27.3,11.91 27.62,11.59 27.62,7.14 R17.1
N$15  (via drill 0.3)
  Top 0.203: IC3.6 7.78,13.97 6.83,14.92 v6.83,18.1 | v10.16,20.64 IC1.12
  Bottom 0.203: v6.83,18.1 7.62,18.1 v10.16,20.64
N$16  (via drill 0.3)
  Top 0.203: v11.43,20.64 IC1.14 | IC3.1 5.58,15.26 6.19,15.88 v6.19,17.46
  Bottom 0.203: v11.43,20.64 11.43,20.32 8.57,17.46 v6.19,17.46
N$17
  Top 0.406: IC8.7 65.72,20.95 66.36,21.59 66.36,22.86 66.04,23.18 62.55,23.18 R7.1
N$18  (via drill 0.3)
  Top 0.203: IC3.4 4.84,13.31 C2.1 | C2.1 6.35,11.8 | v7.62,11.11 7.04,11.11 C2.1 | IC4.2 30.8,13.35 v30.8,13.97
  Bottom 0.203: v7.62,11.11 10.48,8.26 25.08,8.26 v30.8,13.97
N$21
  Top 0.203: IC9.1 15.43,14.61 R9.1
N$22
  Top 0.203: IC9.2 14.5,14.02 13.65,13.18 R14.2
N$23
  Top 0.203: 12.54,8.89 R16.2 12.6,9.21 13.02,9.21 13.81,10 13.81,11.43 14.45,12.07 IC9.5
N$25
  Top 0.203: IC9.18 22.1,13.37 22.54,13.81 25.98,13.81 R15.1
N$26
  Top 0.203: 12.46,10.5 R19.2 12.6,10.64 13.02,10.64 13.34,10.95 13.34,11.59 14.47,12.72 IC9.4
N$27
  Top 0.203: IC9.20 23.03,14.67 R11.1
OP-VCC
  Top 0.203: IC10.8 11.75,2.44 11.75,1.05 C14.1 L2.2
VCC  (via drill 0.3)
  Top 0.203: IC9.13 IC9.14 21.31,10.79 20.32,10.79 20.32,15.08 C23.1 19.36,16.2 18.41,17.14 16.67,17.14 v14.13,19.68 13.18,18.73 9.84,18.73 9.53,18.41 9.53,16.03 | 9.53,10.32 9.53,8.89 R16.1 | 9.53,10.32 9.53,11.75 | 9.53,11.75 9.53,13.18 | 9.53,13.18 9.53,14.61 | 9.53,14.61 9.53,16.03 | R16.1 | 9.53,10.32 R19.1 | 9.53,11.75 R13.1 | 9.53,13.18 R14.1 | 9.53,14.61 R9.2 | 9.53,16.03 R10.2 | 9.53,16.03
  Top 0.406: IC8.1 59.69,22.23 60.96,20.95 60.96,19.68 | 60.96,19.68 IC8.3 56.65,19.68 C12.1 v55.88,18.1 | 60.96,19.68 IC8.6 | F1.2 21.27,28.57 | F1.2 22.23,27.75 | C8.1 16.2,26.04 17.3,27.15 19.97,27.15 F1.2 | IC5.8 16.93,25.62 C8.1 | v16.19,25.08 C8.1 | IC5.5 21.59,28.39 F1.2 | v45.4,20 44.13,20
  Top 0.61: R22.1 32.54,19.37
  Bottom 0.406: v55.88,18.1 53.98,20 v45.4,20 | v14.13,19.68 14.13,23.02 v16.19,25.08
  pour Top (no thermals): 20.95,29.21 22.54,29.21 26.35,25.4 26.35,22.23 27.3,21.27 28.57,21.27 32.07,24.77 32.07,35.24 40.96,35.24 44.45,31.75 44.45,19.68 34.29,19.68 33.66,19.05 27.62,19.05 24.77,21.91 24.77,25.08 21.91,27.94 20.95,27.94
VDRAIN
  Top 0.203: Q1.8 30.48,11.11 | 29.53,11.11 29.21,11.43 28.57,11.43 27.94,12.06 27.94,13.65 27.09,14.5 R15.2 26.57,14.92 R11.2
  Top 0.61: 32.54,10.48 C25.2
  pour Top (no thermals): 44.45,19.05 44.45,1.27 30.8,1.27 30.8,6.35 30.16,6.99 29.21,6.99 29.21,11.43 33.66,11.43 34.61,12.38 34.61,19.05

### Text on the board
tPlace: + | High Voltage! | Design: A.Ryll | KD v12b | TIGERs Mannheim | +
